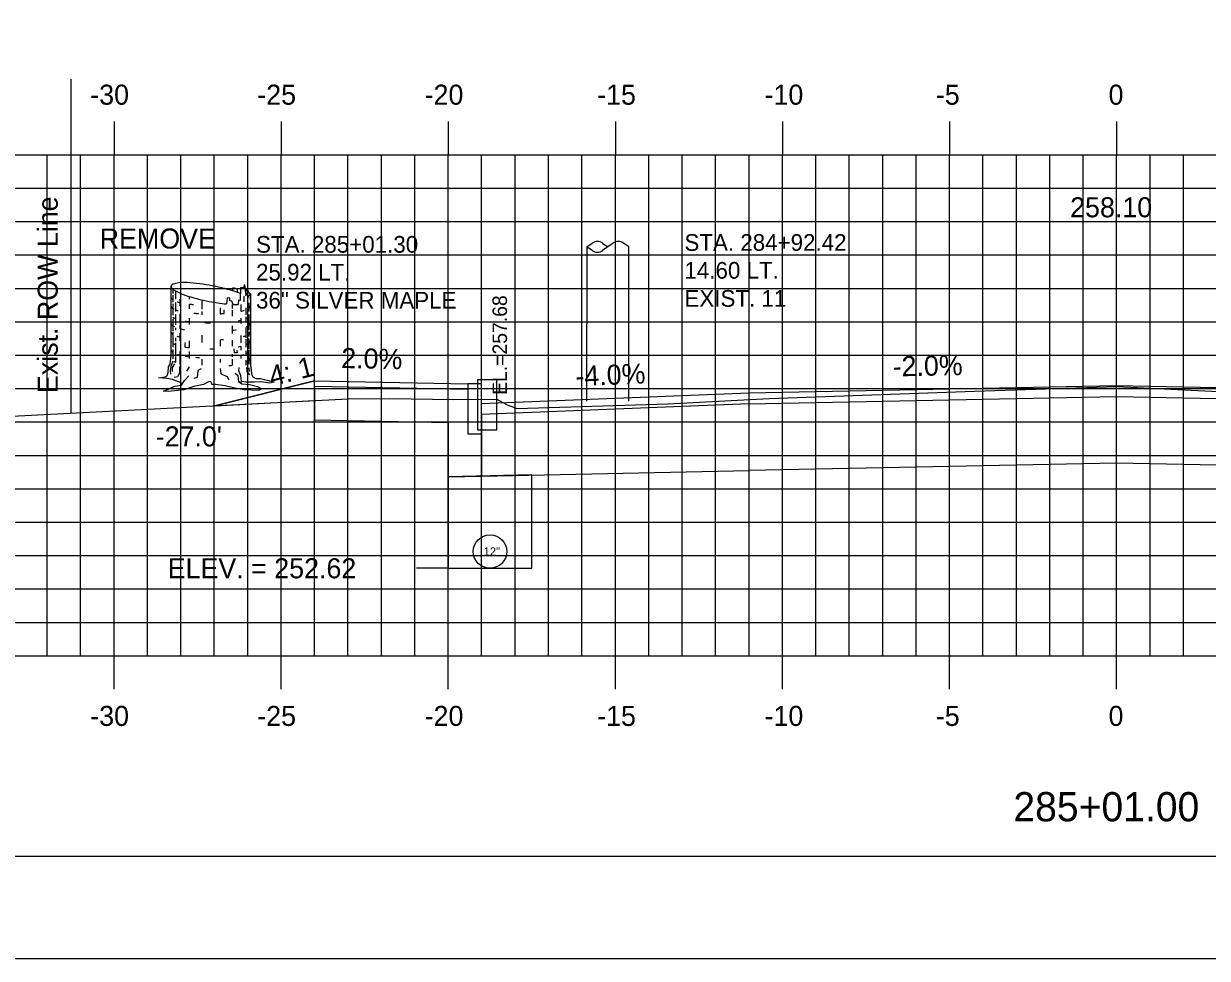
# Model space of a CAD drawing. Extents: x 856680 to 856850, y 366268 to 366378.
# Drawn here: x 856730.41 to 856765.83, y 366268.18 to 366296.16 of the extents above; entities that cross this region are included whole.
import ezdxf

# ---------------------------------------------------------------- set-up
doc = ezdxf.new("R2010")
doc.units = 0
for name, color, linetype in [('ANNOTATION', 7, 'Continuous'), ('BORDER', 7, 'Continuous'), ('D_Curb_Type_1_Lt', 7, 'Continuous'), ('D_Roadway_Centerline_Text', 7, 'Continuous'), ('D_Roadway_Edge_Shoulder', 7, 'Continuous'), ('D_Roadway_FinishedGrade', 7, 'Continuous'), ('D_Roadway_Sidewalks_Paved', 7, 'Continuous'), ('D_Roadway_SubGrade', 7, 'Continuous'), ('D_Text_Monospaced', 7, 'Continuous'), ('D_Text_Standard', 7, 'Continuous'), ('E_ROW_Line', 7, 'Continuous'), ('H_V ANNOTATION', 7, 'Continuous'), ('JUNK FILL', 7, 'Continuous'), ('junk strct exc', 7, 'Continuous'), ('MAJOR', 7, 'Continuous'), ('MINOR', 7, 'Continuous'), ('PDRAIN', 7, 'Continuous'), ('PLOT BOUNDARY', 7, 'Continuous'), ('S_Curb_Type_2', 7, 'Continuous'), ('S_Roadway_Centerline', 7, 'Continuous'), ('S_Trees_Decid_Pay', 7, 'Continuous'), ('S_Utilities_Pole_Power', 7, 'Continuous')]:
    doc.layers.add(name, color=color, linetype=linetype)

msp = doc.modelspace()

# ---------------------------------------------------------------- linework, layer by layer
at = {"layer": 'BORDER'}
msp.add_line((856688.116, 366271.236), (856848.116, 366271.236), dxfattribs=at)
at = {"layer": 'D_Curb_Type_1_Lt'}
msp.add_lwpolyline([(856743.7, 366285.377), (856743.7, 366283.877), (856744.116, 366283.877), (856744.116, 366285.377)], close=True, dxfattribs=at)
at = {"layer": 'D_Roadway_Edge_Shoulder'}
msp.add_lwpolyline([(856744.116, 366284.793), (856752.116, 366285.113), (856763.116, 366285.333), (856774.116, 366285.113), (856782.117, 366284.793)], dxfattribs=at)
at = {"layer": 'D_Roadway_FinishedGrade'}
msp.add_line((856736.13, 366284.723), (856739.111, 366285.468), dxfattribs=at)
at = {"layer": 'D_Roadway_Sidewalks_Paved'}
msp.add_lwpolyline([(856739.111, 366285.468), (856743.7, 366285.377), (856743.7, 366285.21), (856739.111, 366285.302)], close=True, dxfattribs=at)
at = {"layer": 'D_Roadway_SubGrade'}
msp.add_lwpolyline([(856739.111, 366285.302), (856739.111, 366284.302), (856743.116, 366284.221), (856743.116, 366282.599), (856744.116, 366282.619)], dxfattribs=at)
for points in [[(856752.116, 366282.779), (856752.116, 366284.779), (856763.116, 366284.999), (856774.116, 366284.779), (856774.116, 366282.779), (856763.116, 366282.999)], [(856752.116, 366284.779), (856744.116, 366284.459), (856744.116, 366282.619), (856752.116, 366282.779)]]:
    msp.add_lwpolyline(points, close=True, dxfattribs=at)
at = {"layer": 'D_Text_Standard'}
msp.add_lwpolyline([(856743.116, 366279.856), (856742.85, 366279.856), (856742.17, 366279.856)], dxfattribs=at)
at = {"layer": 'E_ROW_Line'}
msp.add_line((856731.831, 366284.503), (856731.831, 366294.503), dxfattribs=at)
at = {"layer": 'JUNK FILL'}
msp.add_lwpolyline([(856739.116, 366284.876), (856739.116, 366285.468), (856739.111, 366285.468), (856736.13, 366284.723)], close=True, dxfattribs=at)
at = {"layer": 'junk strct exc'}
msp.add_lwpolyline([(856743.116, 366282.599), (856743.116, 366279.856), (856745.616, 366279.856), (856745.616, 366282.649)], close=True, dxfattribs=at)
at = {"layer": 'MAJOR'}
for p, q in [((856733.116, 366293.238), (856733.116, 366292.236)), ((856738.116, 366293.238), (856738.116, 366292.236)), ((856743.116, 366293.238), (856743.116, 366292.236)), ((856748.116, 366293.238), (856748.116, 366292.236)), ((856753.116, 366293.238), (856753.116, 366292.236)), ((856758.116, 366293.238), (856758.116, 366292.236)), ((856763.116, 366293.238), (856763.116, 366292.236)), ((856693.116, 366292.236), (856833.116, 366292.236)), ((856693.116, 366292.236), (856833.116, 366292.236)), ((856733.116, 366277.236), (856733.116, 366292.236)), ((856738.116, 366277.236), (856738.116, 366292.236)), ((856743.116, 366277.236), (856743.116, 366292.236)), ((856748.116, 366277.236), (856748.116, 366292.236)), ((856753.116, 366277.236), (856753.116, 366292.236)), ((856758.116, 366277.236), (856758.116, 366292.236)), ((856763.116, 366277.236), (856763.116, 366292.236)), ((856693.116, 366287.236), (856833.116, 366287.236)), ((856693.116, 366282.236), (856833.116, 366282.236)), ((856693.116, 366277.236), (856833.116, 366277.236)), ((856693.116, 366277.236), (856833.116, 366277.236)), ((856733.116, 366276.234), (856733.116, 366277.236)), ((856738.116, 366276.234), (856738.116, 366277.236)), ((856743.116, 366276.234), (856743.116, 366277.236)), ((856748.116, 366276.234), (856748.116, 366277.236)), ((856753.116, 366276.234), (856753.116, 366277.236)), ((856758.116, 366276.234), (856758.116, 366277.236)), ((856763.116, 366276.234), (856763.116, 366277.236))]:
    msp.add_line(p, q, dxfattribs=at)
at = {"layer": 'MINOR'}
for p, q in [((856731.116, 366277.236), (856731.116, 366292.236)), ((856732.116, 366277.236), (856732.116, 366292.236)), ((856734.116, 366277.236), (856734.116, 366292.236)), ((856735.116, 366277.236), (856735.116, 366292.236)), ((856736.116, 366277.236), (856736.116, 366292.236)), ((856737.116, 366277.236), (856737.116, 366292.236)), ((856739.116, 366277.236), (856739.116, 366292.236)), ((856740.116, 366277.236), (856740.116, 366292.236)), ((856741.116, 366277.236), (856741.116, 366292.236)), ((856742.116, 366277.236), (856742.116, 366292.236)), ((856744.116, 366277.236), (856744.116, 366292.236)), ((856745.116, 366277.236), (856745.116, 366292.236)), ((856746.116, 366277.236), (856746.116, 366292.236)), ((856747.116, 366277.236), (856747.116, 366292.236)), ((856749.116, 366277.236), (856749.116, 366292.236)), ((856750.116, 366277.236), (856750.116, 366292.236)), ((856751.116, 366277.236), (856751.116, 366292.236)), ((856752.116, 366277.236), (856752.116, 366292.236)), ((856754.116, 366277.236), (856754.116, 366292.236)), ((856755.116, 366277.236), (856755.116, 366292.236)), ((856756.116, 366277.236), (856756.116, 366292.236)), ((856757.116, 366277.236), (856757.116, 366292.236)), ((856759.116, 366277.236), (856759.116, 366292.236)), ((856760.116, 366277.236), (856760.116, 366292.236)), ((856761.116, 366277.236), (856761.116, 366292.236)), ((856762.116, 366277.236), (856762.116, 366292.236)), ((856764.116, 366277.236), (856764.116, 366292.236)), ((856765.116, 366277.236), (856765.116, 366292.236)), ((856693.116, 366291.236), (856833.116, 366291.236)), ((856693.116, 366290.236), (856833.116, 366290.236)), ((856693.116, 366289.236), (856833.116, 366289.236)), ((856693.116, 366288.236), (856833.116, 366288.236)), ((856693.116, 366286.236), (856833.116, 366286.236)), ((856693.116, 366285.236), (856833.116, 366285.236)), ((856693.116, 366284.236), (856833.116, 366284.236)), ((856693.116, 366283.236), (856833.116, 366283.236)), ((856693.116, 366281.236), (856833.116, 366281.236)), ((856693.116, 366280.236), (856833.116, 366280.236)), ((856693.116, 366279.236), (856833.116, 366279.236)), ((856693.116, 366278.236), (856833.116, 366278.236))]:
    msp.add_line(p, q, dxfattribs=at)
at = {"layer": 'PDRAIN'}
msp.add_lwpolyline([(856743.116, 366282.599), (856743.116, 366279.856), (856745.616, 366279.856), (856745.616, 366282.649)], dxfattribs=at)
msp.add_circle((856744.366, 366280.356), 0.5, dxfattribs=at)
at = {"layer": 'PLOT BOUNDARY'}
msp.add_lwpolyline([(856680.023, 366268.177), (856850.023, 366268.177), (856850.023, 366378.177), (856680.023, 366378.177)], close=True, dxfattribs=at)
at = {"layer": 'S_Curb_Type_2'}
msp.add_lwpolyline([(856744.573, 366285.502), (856743.989, 366285.502), (856743.989, 366284.002), (856744.573, 366284.002)], close=True, dxfattribs=at)
at = {"layer": 'S_Roadway_Centerline'}
msp.add_lwpolyline([(856726.957, 366284.253), (856740.121, 366284.928), (856741.371, 366284.942), (856743.287, 366284.909), (856744.573, 366284.919), (856744.863, 366284.759), (856745.173, 366284.642), (856749.687, 366284.775), (856752.722, 366284.944), (856758.868, 366285.156), (856763.12, 366285.297), (856769.599, 366284.982), (856773.753, 366284.86), (856775.579, 366284.829), (856779.107, 366284.922), (856779.312, 366284.832), (856779.656, 366284.734), (856781.549, 366284.779), (856783.225, 366284.802), (856786.527, 366284.756), (856789.691, 366284.768), (856791.541, 366284.755), (856792.375, 366284.743)], dxfattribs=at)
at = {"layer": 'S_Trees_Decid_Pay'}
for p, q in [((856734.874, 366288.207), (856734.874, 366288.086)), ((856734.874, 366288.034), (856734.874, 366287.82)), ((856734.954, 366288.162), (856734.954, 366287.909)), ((856736.999, 366288.003), (856736.999, 366287.829)), ((856734.874, 366287.775), (856734.874, 366287.437)), ((856734.954, 366287.812), (856734.954, 366287.548)), ((856735.087, 366287.909), (856735.087, 366287.717)), ((856735.359, 366287.995), (856735.359, 366287.909)), ((856735.359, 366287.768), (856735.359, 366287.628)), ((856735.742, 366287.894), (856735.742, 366287.614)), ((856736.288, 366287.657), (856736.288, 366287.478)), ((856736.653, 366287.756), (856736.653, 366287.637)), ((856736.914, 366287.754), (856736.914, 366287.55)), ((856737.062, 366287.657), (856737.062, 366287.445)), ((856737.148, 366287.803), (856737.148, 366287.548)), ((856734.874, 366287.32), (856734.874, 366286.959)), ((856734.954, 366287.451), (856734.954, 366287.143)), ((856735.087, 366287.466), (856735.087, 366287.188)), ((856735.359, 366287.342), (856735.359, 366287.151)), ((856735.742, 366287.548), (856735.742, 366287.445)), ((856736.415, 366287.485), (856736.409, 366287.592)), ((856736.653, 366287.585), (856736.653, 366287.4)), ((856736.914, 366287.342), (856736.914, 366287.188)), ((856737.062, 366287.38), (856737.062, 366287.232)), ((856737.148, 366287.451), (856737.148, 366286.982)), ((856734.954, 366287.054), (856734.954, 366286.988)), ((856735.087, 366287.143), (856735.087, 366287.034)), ((856736.653, 366287.114), (856736.653, 366286.886)), ((856737.062, 366287.054), (856737.062, 366286.754)), ((856734.874, 366286.922), (856734.874, 366286.474)), ((856734.954, 366286.754), (856734.954, 366286.657)), ((856734.954, 366286.606), (856734.954, 366286.245)), ((856735.087, 366286.899), (856735.087, 366286.671)), ((856735.359, 366286.671), (856735.359, 366286.463)), ((856735.742, 366286.834), (856735.742, 366286.613)), ((856736.288, 366286.699), (856736.288, 366286.503)), ((856736.653, 366286.688), (856736.653, 366286.503)), ((856736.914, 366286.825), (856736.914, 366286.606)), ((856737.062, 366286.716), (856737.062, 366286.474)), ((856737.148, 366286.931), (856737.148, 366286.797)), ((856737.148, 366286.739), (856737.148, 366286.414)), ((856734.874, 366286.408), (856734.874, 366286.126)), ((856735.087, 366286.342), (856735.087, 366285.959)), ((856735.359, 366286.342), (856735.359, 366286.142)), ((856736.653, 366286.268), (856736.653, 366286.191)), ((856736.914, 366286.506), (856736.914, 366286.385)), ((856736.914, 366286.234), (856736.914, 366286.136)), ((856737.062, 366286.363), (856737.062, 366286.222)), ((856737.148, 366286.385), (856737.148, 366285.965)), ((856734.954, 366286.193), (856734.954, 366286.027)), ((856735.364, 366285.885), (856735.283, 366285.753)), ((856735.742, 366286.113), (856735.742, 366285.94)), ((856736.288, 366286.119), (856736.288, 366286.016)), ((856736.653, 366286.113), (856736.653, 366285.94)), ((856737.062, 366286.09), (856737.062, 366285.934)), ((856737.145, 366285.862), (856737.159, 366285.745))]:
    msp.add_line(p, q, dxfattribs=at)
for points in [[(856737.199, 366288.077), (856737.199, 366285.94), (856737.219, 366285.798), (856737.225, 366285.672), (856737.268, 366285.586), (856737.361, 366285.537), (856737.497, 366285.537), (856737.74, 366285.481), (856737.907, 366285.432), (856737.764, 366285.401), (856737.528, 366285.438), (856737.318, 366285.426), (856737.056, 366285.432), (856736.932, 366285.45), (856736.902, 366285.407), (856736.84, 366285.45), (856736.939, 366285.382), (856737.174, 366285.357), (856737.404, 366285.296), (856737.534, 366285.226), (856737.435, 366285.182), (856737.013, 366285.201), (856736.735, 366285.245), (856736.436, 366285.321), (856736.15, 366285.357), (856736.045, 366285.357), (856736.027, 366285.438), (856735.959, 366285.444), (856735.792, 366285.357), (856735.506, 366285.302), (856735.207, 366285.195), (856734.748, 366285.146), (856734.594, 366285.158), (856734.936, 366285.308), (856735.139, 366285.339), (856735.127, 366285.413), (856734.867, 366285.512), (856734.692, 366285.543), (856734.451, 366285.555), (856734.65, 366285.592), (856734.711, 366285.629), (856734.736, 366285.716), (856734.748, 366285.885), (856734.793, 366285.971), (856734.822, 366286.212), (856734.822, 366288.298)], [(856736.82, 366288.116), (856736.799, 366288.224), (856736.667, 366288.254), (856736.66, 366288.167)], [(856736.843, 366287.75), (856736.85, 366287.894), (856736.896, 366287.886), (856736.91, 366288.261), (856737.005, 366288.269), (856737.019, 366288.349), (856737.056, 366288.012), (856737.102, 366288.106), (856737.122, 366287.952), (856737.199, 366288.077), (856737.193, 366287.888)], [(856737.199, 366288.077), (856737.153, 366288.1), (856737.131, 366288.166), (856737.079, 366288.189), (856737.045, 366288.114)], [(856736.681, 366287.754), (856736.644, 366287.857), (856736.579, 366287.863), (856736.579, 366287.945), (856736.505, 366287.952), (856736.48, 366287.772)], [(856735.245, 366286.477), (856735.247, 366286.554), (856735.255, 366286.62)], [(856736.791, 366286.385), (856736.799, 366286.311), (856736.725, 366286.305), (856736.711, 366286.422)], [(856734.872, 366286.054), (856734.812, 366285.893), (856734.798, 366285.768), (856734.806, 366285.67)], [(856734.929, 366285.973), (856734.858, 366285.87), (856734.858, 366285.745)], [(856735.07, 366285.899), (856735.07, 366285.693), (856735.012, 366285.584), (856734.915, 366285.567)], [(856735.139, 366285.339), (856735.226, 366285.481), (856735.358, 366285.623)], [(856735.724, 366285.825), (856735.621, 366285.774), (856735.607, 366285.567), (856735.504, 366285.539)], [(856736.29, 366285.833), (856736.307, 366285.679), (856736.505, 366285.598), (856736.55, 366285.495)], [(856736.741, 366285.697), (856736.816, 366285.629), (856736.834, 366285.531), (856736.84, 366285.45)], [(856736.932, 366285.45), (856736.914, 366285.629), (856736.852, 366285.766), (856736.859, 366285.866)], [(856737.079, 366285.87), (856737.085, 366285.745), (856737.167, 366285.65)]]:
    msp.add_lwpolyline(points, dxfattribs=at)
for centre, radius, start, end in [((856734.945, 366288.212), 0.164, 110.0157, 124.2221), ((856735.053, 366287.915), 0.48, 101.7221, 110.0157), ((856735.22, 366287.113), 1.299, 86.3056, 101.7221), ((856734.909, 366282.296), 6.126, 79.2221, 86.3056), ((856734.868, 366288.298), 0.0467, 169.2221, 180.9043), ((856734.876, 366288.298), 0.0544, 180.9043, 191.7221), ((856734.868, 366288.298), 0.0467, 157.54, 169.2221), ((856734.886, 366288.3), 0.0645, 191.7221, 204.3989), ((856734.875, 366288.295), 0.0544, 146.7221, 157.54), ((856734.925, 366288.318), 0.107, 204.3989, 214.2221), ((856734.884, 366288.289), 0.0645, 134.0453, 146.7221), ((856734.972, 366288.35), 0.164, 214.2221, 228.4286), ((856734.913, 366288.259), 0.107, 124.2221, 134.0453), ((856735.181, 366288.586), 0.48, 228.4286, 236.7221), ((856735.631, 366289.271), 1.299, 236.7221, 252.1387), ((856737.111, 366293.865), 6.126, 252.1387, 259.2221), ((856734.909, 366282.296), 6.126, 72.1387, 79.2221), ((856736.389, 366286.89), 1.299, 66.6931, 72.1387), ((856734.876, 366287.971), 0.0554, 191.6815, 202.5), ((856734.877, 366287.711), 0.0554, 191.6815, 202.5), ((856734.885, 366287.975), 0.0657, 202.5, 215.1737), ((856734.886, 366287.714), 0.0657, 202.5, 215.1737), ((856734.921, 366288), 0.109, 215.1737, 225), ((856734.922, 366287.739), 0.109, 215.1737, 225), ((856734.961, 366288.041), 0.166, 225, 238.33), ((856734.962, 366287.78), 0.166, 225, 239.1924), ((856735.433, 366289.06), 1.292, 250.9084, 254.4349), ((856736.009, 366293.648), 5.916, 263.6913, 265.0485), ((856737.111, 366293.865), 6.126, 259.2221, 264.0853), ((856737.111, 366293.865), 6.126, 265.9754, 266.3056), ((856736.8, 366289.049), 1.299, 266.3056, 271.8711), ((856737.058, 366287.78), 0.166, 300.8076, 315), ((856737.098, 366287.739), 0.109, 315, 324.8263), ((856737.134, 366287.714), 0.0657, 324.8263, 337.5), ((856737.143, 366287.711), 0.0554, 337.5, 348.3185), ((856737.151, 366287.709), 0.0476, 348.3185, 0), ((856734.962, 366287.517), 0.166, 238.3999, 239.1924), ((856735.125, 366288.053), 0.484, 239.1924, 242.5838), ((856735.125, 366287.789), 0.484, 239.1924, 247.5), ((856735.434, 366288.799), 1.292, 247.5, 251.9171), ((856735.434, 366288.536), 1.292, 247.5, 248.1929), ((856736.01, 366293.387), 5.916, 265.1076, 266.4618), ((856736.01, 366293.387), 5.916, 272.6957, 273.9224), ((856736.586, 366288.799), 1.292, 284.7144, 289.3881), ((856736.586, 366288.536), 1.292, 291.6463, 292.5), ((856736.895, 366287.789), 0.484, 292.5, 300.8076), ((856737.058, 366287.517), 0.166, 300.8076, 302.9622), ((856734.877, 366287.19), 0.0554, 191.6815, 202.5), ((856734.886, 366287.194), 0.0657, 202.5, 215.1737), ((856734.922, 366287.219), 0.109, 215.1737, 225), ((856734.962, 366287.259), 0.166, 225, 239.1924), ((856735.125, 366287.532), 0.484, 239.1924, 245.3628), ((856735.434, 366288.278), 1.292, 254.3895, 260.7435), ((856735.434, 366288.536), 1.292, 261.6338, 262.8454), ((856736.01, 366293.124), 5.916, 262.8454, 263.6816), ((856736.01, 366293.124), 5.916, 268.2292, 269.8838), ((856736.01, 366292.866), 5.916, 276.2405, 277.1546), ((856736.586, 366288.278), 1.292, 277.1546, 278.1274), ((856736.586, 366288.536), 1.292, 280.7368, 284.7144), ((856736.586, 366288.278), 1.292, 291.5158, 292.5), ((856736.895, 366287.532), 0.484, 294.2275, 300.8076), ((856737.058, 366287.259), 0.166, 300.8076, 315), ((856737.098, 366287.219), 0.109, 315, 324.8263), ((856737.134, 366287.194), 0.0657, 324.8263, 337.5), ((856737.143, 366287.19), 0.0554, 337.5, 348.3185), ((856737.151, 366287.188), 0.0476, 348.3185, 0), ((856734.877, 366286.932), 0.0554, 191.6815, 202.5), ((856734.877, 366286.667), 0.0554, 191.6815, 202.5), ((856734.886, 366286.936), 0.0657, 202.5, 215.1737), ((856734.922, 366286.961), 0.109, 215.1737, 225), ((856734.962, 366287.002), 0.166, 225, 237.9306), ((856734.962, 366286.736), 0.166, 237.9306, 239.1924), ((856735.125, 366287.009), 0.484, 239.1924, 247.5), ((856735.434, 366288.021), 1.292, 249.8999, 254.3895), ((856736.01, 366292.609), 5.916, 272.6957, 273.7279), ((856736.586, 366288.021), 1.292, 288.201, 292.5), ((856736.895, 366287.009), 0.484, 292.5, 300.8076), ((856737.058, 366287.002), 0.166, 300.8076, 315), ((856737.058, 366286.736), 0.166, 300.8076, 315), ((856737.098, 366286.961), 0.109, 315, 324.8263), ((856737.098, 366286.696), 0.109, 315, 324.8263), ((856737.134, 366286.936), 0.0657, 324.8263, 337.5), ((856737.134, 366286.671), 0.0657, 324.8263, 337.5), ((856737.143, 366286.932), 0.0554, 337.5, 348.3185), ((856737.143, 366286.667), 0.0554, 337.5, 348.3185), ((856737.151, 366286.931), 0.0476, 348.3185, 0), ((856737.151, 366286.665), 0.0476, 348.3185, 0), ((856734.877, 366286.395), 0.0554, 191.6815, 202.5), ((856734.886, 366286.399), 0.0657, 202.5, 215.1737), ((856734.922, 366286.424), 0.109, 215.1737, 225), ((856734.962, 366286.464), 0.166, 225, 237.9306), ((856735.434, 366287.484), 1.292, 250.8466, 254.3895), ((856735.434, 366287.755), 1.292, 261.6205, 262.8454), ((856736.01, 366292.343), 5.916, 262.8454, 263.6816), ((856736.01, 366292.343), 5.916, 269.7243, 270), ((856736.01, 366292.343), 5.916, 270, 271.0793), ((856736.586, 366287.755), 1.292, 280.7537, 284.7144), ((856736.586, 366287.484), 1.292, 284.7144, 288.6336), ((856736.586, 366287.755), 1.292, 291.6463, 292.5), ((856736.895, 366286.737), 0.484, 292.5, 297.266), ((856735.125, 366286.48), 0.484, 243.4501, 247.5), ((856735.425, 366287.23), 1.292, 247.9396, 248.6304), ((856735.434, 366287.484), 1.292, 261.6338, 262.8454), ((856736.01, 366292.072), 5.916, 262.8454, 263.6816), ((856736.01, 366292.072), 5.916, 265.539, 266.7363), ((856736.01, 366291.814), 5.916, 275.2344, 276.2169), ((856736.586, 366287.226), 1.292, 291.6463, 292.5), ((856736.895, 366286.48), 0.484, 292.5, 300.8076), ((856737.058, 366286.207), 0.166, 300.8076, 315), ((856737.098, 366286.166), 0.109, 315, 324.8263), ((856737.134, 366286.141), 0.0657, 324.8263, 337.5), ((856737.143, 366286.137), 0.0554, 337.5, 348.3185), ((856737.151, 366286.136), 0.0476, 348.3185, 0)]:
    msp.add_arc(centre, radius, start, end, dxfattribs=at)
at = {"layer": 'S_Utilities_Pole_Power'}
for p, q in [((856747.267, 366289.482), (856747.423, 366289.592)), ((856747.267, 366284.863), (856747.271, 366289.482)), ((856747.423, 366289.371), (856747.267, 366289.482)), ((856747.736, 366289.592), (856747.893, 366289.482)), ((856747.893, 366289.482), (856747.736, 366289.371)), ((856748.049, 366289.592), (856747.893, 366289.482)), ((856748.517, 366289.482), (856748.361, 366289.592)), ((856748.517, 366284.863), (856748.521, 366289.482))]:
    msp.add_line(p, q, dxfattribs=at)
for centre, start, end in [((856747.58, 366289.372), 90, 125.2644), ((856747.58, 366289.372), 54.7356, 90), ((856748.205, 366289.372), 90, 125.2644), ((856748.205, 366289.372), 54.7356, 90), ((856747.58, 366289.593), 234.7356, 270), ((856747.58, 366289.593), 270, 305.2644)]:
    msp.add_arc(centre, 0.271, start, end, dxfattribs=at)

# ---------------------------------------------------------------- texts
at = {"layer": 'ANNOTATION'}
msp.add_text('REMOVE', height=0.6, dxfattribs=at).set_placement((856732.687, 366289.429))
for s, rotation, p in [('2.0%', 358.8542, (856739.909, 366285.853)), ('-2.0%', 1.1458, (856756.419, 366285.599)), ('4: 1', 14.0362, (856737.841, 366285.305)), ('-4.0%', 2.2906, (856746.932, 366285.307))]:
    msp.add_text(s, height=0.6, rotation=rotation, dxfattribs=at).set_placement(p)
at = {"layer": 'D_Roadway_Centerline_Text'}
msp.add_text('258.10', height=0.6, dxfattribs=at).set_placement((856761.725, 366290.365))
at = {"layer": 'D_Text_Monospaced'}
for s, height, p in [('STA. 285+01.30', 0.49998, (856737.365, 366289.305)), ('STA. 284+92.42', 0.49998, (856750.184, 366289.361)), ('25.92 LT.', 0.5, (856737.365, 366288.471)), ('14.60 LT.', 0.5, (856750.184, 366288.527)), ('36" SILVER MAPLE', 0.49998, (856737.365, 366287.631)), ('EXIST. 11', 0.5, (856750.184, 366287.687))]:
    msp.add_text(s, height=height, dxfattribs=at).set_placement(p)
at = {"layer": 'D_Text_Standard'}
msp.add_text(' EL.=257.68', height=0.4335, rotation=90, dxfattribs=at).set_placement((856744.874, 366284.887))
for s, p in [("-27.0'", (856734.363, 366283.505)), ('ELEV. = 252.62', (856734.721, 366279.556))]:
    msp.add_text(s, height=0.6, dxfattribs=at).set_placement(p)
at = {"layer": 'E_ROW_Line'}
msp.add_text('Exist. ROW Line', height=0.6, rotation=90, dxfattribs=at).set_placement((856731.431, 366285.103))
at = {"layer": 'H_V ANNOTATION'}
for s, height, p in [('-30', 0.6, (856732.404, 366293.736)), ('-25', 0.6, (856737.402, 366293.736)), ('-20', 0.6, (856742.41, 366293.736)), ('-15', 0.6, (856747.573, 366293.736)), ('-10', 0.6, (856752.581, 366293.736)), ('-5', 0.6, (856757.707, 366293.736)), ('0', 0.6, (856762.875, 366293.736)), ('-30', 0.6, (856732.404, 366275.136)), ('-25', 0.6, (856737.402, 366275.136)), ('-20', 0.6, (856742.41, 366275.136)), ('-15', 0.6, (856747.573, 366275.136)), ('-10', 0.6, (856752.581, 366275.136)), ('-5', 0.6, (856757.707, 366275.136)), ('0', 0.6, (856762.875, 366275.136)), ('285+01.00', 0.875, (856760.026, 366272.28))]:
    msp.add_text(s, height=height, dxfattribs=at).set_placement(p)
at = {"layer": 'PDRAIN'}
msp.add_text('12"', height=0.25, dxfattribs=at).set_placement((856744.175, 366280.232))
at = {"layer": 'S_Roadway_Centerline'}
for s, p in [('C', (856763.114, 366285.297)), ('L', (856763.12, 366285.29))]:
    msp.add_text(s, height=0.0146, dxfattribs=at).set_placement(p)

doc.saveas('drawing.dxf')
